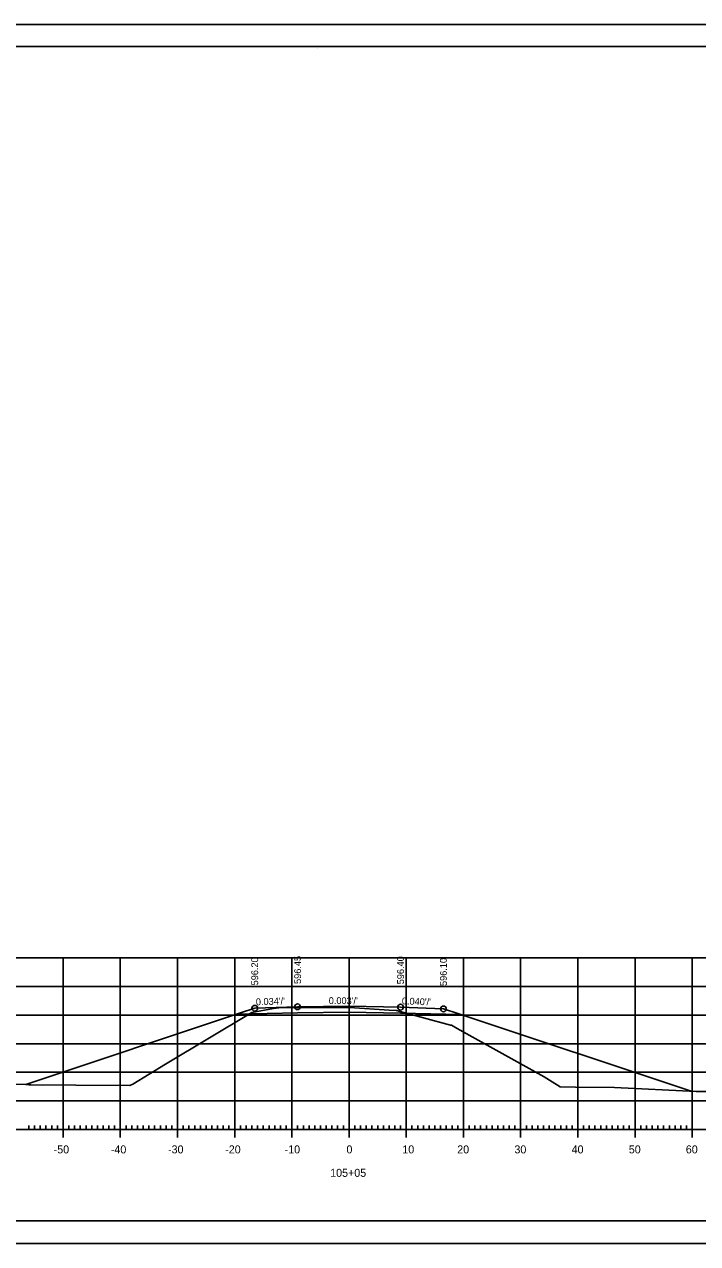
# Model space of a CAD drawing. Extents: x 961436 to 1372525, y 380079 to 2027791.
# Drawn here: x 1372305 to 1372422.8, y 380679.4 to 380892.8 of the extents above; entities that cross this region are included whole.
import ezdxf

# ---------------------------------------------------------------- set-up
doc = ezdxf.new("R2010")
doc.units = 0
for name, color, linetype in [('R_Alt Surface', 7, 'Continuous'), ('R_Axis', 7, 'Continuous'), ('R_Axis Annot', 7, 'Continuous'), ('R_Border', 7, 'Continuous'), ('R_Exist Surface', 7, 'Continuous'), ('R_Fin Surface', 7, 'Continuous'), ('R_Fin Surface Annot', 7, 'Continuous'), ('R_Grid', 7, 'Continuous'), ('R_No Plot', 7, 'Continuous')]:
    doc.layers.add(name, color=color, linetype=linetype)

msp = doc.modelspace()

# ---------------------------------------------------------------- linework, layer by layer
at = {"layer": 'R_Alt Surface'}
for points in [[(1372345.31, 380720.62), (1372342.81, 380719.79)], [(1372378.31, 380720.51), (1372380.81, 380719.68)], [(1372342.81, 380719.79), (1372305.27, 380707.27)], [(1372342.17, 380719.57), (1372352.81, 380719.79), (1372361.81, 380719.92), (1372370.81, 380719.73), (1372381.34, 380719.5)], [(1372380.81, 380719.68), (1372421.6, 380706.08)]]:
    msp.add_lwpolyline(points, dxfattribs=at)
at = {"layer": 'R_Axis'}
for p, q in [((1372221.81, 380699.42), (1372501.81, 380699.42)), ((1372305.81, 380699.42), (1372305.81, 380700.12)), ((1372306.81, 380699.42), (1372306.81, 380700.12)), ((1372307.81, 380699.42), (1372307.81, 380700.12)), ((1372308.81, 380699.42), (1372308.81, 380700.12)), ((1372309.81, 380699.42), (1372309.81, 380700.12)), ((1372310.81, 380699.42), (1372310.81, 380700.12)), ((1372311.81, 380698.02), (1372311.81, 380700.82)), ((1372312.81, 380699.42), (1372312.81, 380700.12)), ((1372313.81, 380699.42), (1372313.81, 380700.12)), ((1372314.81, 380699.42), (1372314.81, 380700.12)), ((1372315.81, 380699.42), (1372315.81, 380700.12)), ((1372316.81, 380699.42), (1372316.81, 380700.12)), ((1372317.81, 380699.42), (1372317.81, 380700.12)), ((1372318.81, 380699.42), (1372318.81, 380700.12)), ((1372319.81, 380699.42), (1372319.81, 380700.12)), ((1372320.81, 380699.42), (1372320.81, 380700.12)), ((1372321.81, 380698.02), (1372321.81, 380700.82)), ((1372322.81, 380699.42), (1372322.81, 380700.12)), ((1372323.81, 380699.42), (1372323.81, 380700.12)), ((1372324.81, 380699.42), (1372324.81, 380700.12)), ((1372325.81, 380699.42), (1372325.81, 380700.12)), ((1372326.81, 380699.42), (1372326.81, 380700.12)), ((1372327.81, 380699.42), (1372327.81, 380700.12)), ((1372328.81, 380699.42), (1372328.81, 380700.12)), ((1372329.81, 380699.42), (1372329.81, 380700.12)), ((1372330.81, 380699.42), (1372330.81, 380700.12)), ((1372331.81, 380698.02), (1372331.81, 380700.82)), ((1372332.81, 380699.42), (1372332.81, 380700.12)), ((1372333.81, 380699.42), (1372333.81, 380700.12)), ((1372334.81, 380699.42), (1372334.81, 380700.12)), ((1372335.81, 380699.42), (1372335.81, 380700.12)), ((1372336.81, 380699.42), (1372336.81, 380700.12)), ((1372337.81, 380699.42), (1372337.81, 380700.12)), ((1372338.81, 380699.42), (1372338.81, 380700.12)), ((1372339.81, 380699.42), (1372339.81, 380700.12)), ((1372340.81, 380699.42), (1372340.81, 380700.12)), ((1372341.81, 380698.02), (1372341.81, 380700.82)), ((1372342.81, 380699.42), (1372342.81, 380700.12)), ((1372343.81, 380699.42), (1372343.81, 380700.12)), ((1372344.81, 380699.42), (1372344.81, 380700.12)), ((1372345.81, 380699.42), (1372345.81, 380700.12)), ((1372346.81, 380699.42), (1372346.81, 380700.12)), ((1372347.81, 380699.42), (1372347.81, 380700.12)), ((1372348.81, 380699.42), (1372348.81, 380700.12)), ((1372349.81, 380699.42), (1372349.81, 380700.12)), ((1372350.81, 380699.42), (1372350.81, 380700.12)), ((1372351.81, 380698.02), (1372351.81, 380700.82)), ((1372352.81, 380699.42), (1372352.81, 380700.12)), ((1372353.81, 380699.42), (1372353.81, 380700.12)), ((1372354.81, 380699.42), (1372354.81, 380700.12)), ((1372355.81, 380699.42), (1372355.81, 380700.12)), ((1372356.81, 380699.42), (1372356.81, 380700.12)), ((1372357.81, 380699.42), (1372357.81, 380700.12)), ((1372358.81, 380699.42), (1372358.81, 380700.12)), ((1372359.81, 380699.42), (1372359.81, 380700.12)), ((1372360.81, 380699.42), (1372360.81, 380700.12)), ((1372361.81, 380698.02), (1372361.81, 380700.82)), ((1372362.81, 380699.42), (1372362.81, 380700.12)), ((1372363.81, 380699.42), (1372363.81, 380700.12)), ((1372364.81, 380699.42), (1372364.81, 380700.12)), ((1372365.81, 380699.42), (1372365.81, 380700.12)), ((1372366.81, 380699.42), (1372366.81, 380700.12)), ((1372367.81, 380699.42), (1372367.81, 380700.12)), ((1372368.81, 380699.42), (1372368.81, 380700.12)), ((1372369.81, 380699.42), (1372369.81, 380700.12)), ((1372370.81, 380699.42), (1372370.81, 380700.12)), ((1372371.81, 380698.02), (1372371.81, 380700.82)), ((1372372.81, 380699.42), (1372372.81, 380700.12)), ((1372373.81, 380699.42), (1372373.81, 380700.12)), ((1372374.81, 380699.42), (1372374.81, 380700.12)), ((1372375.81, 380699.42), (1372375.81, 380700.12)), ((1372376.81, 380699.42), (1372376.81, 380700.12)), ((1372377.81, 380699.42), (1372377.81, 380700.12)), ((1372378.81, 380699.42), (1372378.81, 380700.12)), ((1372379.81, 380699.42), (1372379.81, 380700.12)), ((1372380.81, 380699.42), (1372380.81, 380700.12)), ((1372381.81, 380698.02), (1372381.81, 380700.82)), ((1372382.81, 380699.42), (1372382.81, 380700.12)), ((1372383.81, 380699.42), (1372383.81, 380700.12)), ((1372384.81, 380699.42), (1372384.81, 380700.12)), ((1372385.81, 380699.42), (1372385.81, 380700.12)), ((1372386.81, 380699.42), (1372386.81, 380700.12)), ((1372387.81, 380699.42), (1372387.81, 380700.12)), ((1372388.81, 380699.42), (1372388.81, 380700.12)), ((1372389.81, 380699.42), (1372389.81, 380700.12)), ((1372390.81, 380699.42), (1372390.81, 380700.12)), ((1372391.81, 380698.02), (1372391.81, 380700.82)), ((1372392.81, 380699.42), (1372392.81, 380700.12)), ((1372393.81, 380699.42), (1372393.81, 380700.12)), ((1372394.81, 380699.42), (1372394.81, 380700.12)), ((1372395.81, 380699.42), (1372395.81, 380700.12)), ((1372396.81, 380699.42), (1372396.81, 380700.12)), ((1372397.81, 380699.42), (1372397.81, 380700.12)), ((1372398.81, 380699.42), (1372398.81, 380700.12)), ((1372399.81, 380699.42), (1372399.81, 380700.12)), ((1372400.81, 380699.42), (1372400.81, 380700.12)), ((1372401.81, 380698.02), (1372401.81, 380700.82)), ((1372402.81, 380699.42), (1372402.81, 380700.12)), ((1372403.81, 380699.42), (1372403.81, 380700.12)), ((1372404.81, 380699.42), (1372404.81, 380700.12)), ((1372405.81, 380699.42), (1372405.81, 380700.12)), ((1372406.81, 380699.42), (1372406.81, 380700.12)), ((1372407.81, 380699.42), (1372407.81, 380700.12)), ((1372408.81, 380699.42), (1372408.81, 380700.12)), ((1372409.81, 380699.42), (1372409.81, 380700.12)), ((1372410.81, 380699.42), (1372410.81, 380700.12)), ((1372411.81, 380698.02), (1372411.81, 380700.82)), ((1372412.81, 380699.42), (1372412.81, 380700.12)), ((1372413.81, 380699.42), (1372413.81, 380700.12)), ((1372414.81, 380699.42), (1372414.81, 380700.12)), ((1372415.81, 380699.42), (1372415.81, 380700.12)), ((1372416.81, 380699.42), (1372416.81, 380700.12)), ((1372417.81, 380699.42), (1372417.81, 380700.12)), ((1372418.81, 380699.42), (1372418.81, 380700.12)), ((1372419.81, 380699.42), (1372419.81, 380700.12)), ((1372420.81, 380699.42), (1372420.81, 380700.12)), ((1372421.81, 380698.02), (1372421.81, 380700.82))]:
    msp.add_line(p, q, dxfattribs=at)
at = {"layer": 'R_Border'}
for p, q in [((1372203.81, 380888.88), (1372519.99, 380888.88)), ((1372356.33, 380888.62), (1372356.33, 380888.62)), ((1372356.33, 380888.62), (1372356.33, 380888.62)), ((1372519.99, 380683.42), (1372203.81, 380683.42))]:
    msp.add_line(p, q, dxfattribs=at)
at = {"layer": 'R_Exist Surface'}
msp.add_lwpolyline([(1372292.49, 380707.56), (1372305.27, 380707.27), (1372305.83, 380707.24), (1372306.18, 380707.23), (1372314.02, 380707.18), (1372323.49, 380707.08), (1372324.02, 380707.35), (1372329.72, 380710.82), (1372344.82, 380719.87), (1372348.59, 380720.58), (1372349.54, 380720.67), (1372360.56, 380720.74), (1372361.9, 380720.73), (1372368.84, 380720.31), (1372370.12, 380720.22), (1372379.54, 380717.68), (1372379.69, 380717.64), (1372380.73, 380717.08), (1372395.95, 380708.6), (1372398.72, 380706.87), (1372401.4, 380706.81), (1372408.22, 380706.74), (1372422.52, 380706.04), (1372433.52, 380706.04)], dxfattribs=at)
at = {"layer": 'R_Fin Surface'}
msp.add_lwpolyline([(1372345.31, 380720.62), (1372352.81, 380720.87), (1372361.81, 380721.01), (1372370.81, 380720.81), (1372378.31, 380720.51)], dxfattribs=at)
at = {"layer": 'R_Grid'}
for p, q in [((1372221.81, 380729.42), (1372501.81, 380729.42)), ((1372311.81, 380699.42), (1372311.81, 380729.42)), ((1372321.81, 380699.42), (1372321.81, 380729.42)), ((1372331.81, 380699.42), (1372331.81, 380729.42)), ((1372341.81, 380699.42), (1372341.81, 380729.42)), ((1372351.81, 380699.42), (1372351.81, 380729.42)), ((1372361.81, 380699.42), (1372361.81, 380729.42)), ((1372371.81, 380699.42), (1372371.81, 380729.42)), ((1372381.81, 380699.42), (1372381.81, 380729.42)), ((1372391.81, 380699.42), (1372391.81, 380729.42)), ((1372401.81, 380699.42), (1372401.81, 380729.42)), ((1372411.81, 380699.42), (1372411.81, 380729.42)), ((1372421.81, 380699.42), (1372421.81, 380729.42)), ((1372221.81, 380724.42), (1372501.81, 380724.42)), ((1372221.81, 380719.42), (1372501.81, 380719.42)), ((1372221.81, 380714.42), (1372501.81, 380714.42)), ((1372221.81, 380709.42), (1372501.81, 380709.42)), ((1372221.81, 380704.42), (1372501.81, 380704.42)), ((1372221.81, 380699.42), (1372501.81, 380699.42))]:
    msp.add_line(p, q, dxfattribs=at)
at = {"layer": 'R_No Plot'}
for p, q in [((1372191.41, 380892.77), (1372524.74, 380892.77)), ((1372191.41, 380679.44), (1372524.74, 380679.44))]:
    msp.add_line(p, q, dxfattribs=at)
for points in [[(1372191.4, 380892.77), (1372524.74, 380892.77), (1372524.74, 380679.43), (1372191.4, 380679.43)], [(1372437.73, 380888.88), (1372457.35, 380888.88), (1372457.35, 380879), (1372473.46, 380879), (1372496.66, 380879), (1372496.66, 380846.33), (1372519.87, 380846.33), (1372519.99, 380683.42), (1372203.81, 380683.42), (1372203.81, 380888.88)]]:
    msp.add_lwpolyline(points, close=True, dxfattribs=at)
for centre in [(1372345.31, 380720.62), (1372352.81, 380720.87), (1372370.81, 380720.81), (1372378.31, 380720.51)]:
    msp.add_circle(centre, 0.5, dxfattribs=at)

# ---------------------------------------------------------------- texts
at = {"layer": 'R_Axis Annot'}
for s, p in [('-50', (1372310.15, 380695.22)), ('-40', (1372320.15, 380695.22)), ('-30', (1372330.15, 380695.22)), ('-20', (1372340.15, 380695.22)), ('-10', (1372350.54, 380695.22)), ('0', (1372361.35, 380695.22)), ('10', (1372371.12, 380695.22)), ('20', (1372380.72, 380695.22)), ('30', (1372390.72, 380695.22)), ('40', (1372400.72, 380695.22)), ('50', (1372410.72, 380695.22)), ('60', (1372420.69, 380695.22)), ('105+05', (1372358.5, 380691.12))]:
    msp.add_text(s, height=1.4, dxfattribs=at).set_placement(p)
at = {"layer": 'R_Fin Surface Annot'}
for s, rotation, p in [('596.20', 90, (1372345.91, 380724.62)), ('596.45', 90, (1372353.41, 380724.87)), ('596.40', 90, (1372371.41, 380724.81)), ('596.10', 90, (1372378.91, 380724.51)), ("0.034'/'", 1.9252, (1372345.53, 380721.13)), ("0.003'/'", 359.817, (1372358.25, 380721.35)), ("0.040'/'", 357.7094, (1372371.02, 380721.31))]:
    msp.add_text(s, height=1.2, rotation=rotation, dxfattribs=at).set_placement(p)

doc.saveas('drawing.dxf')
